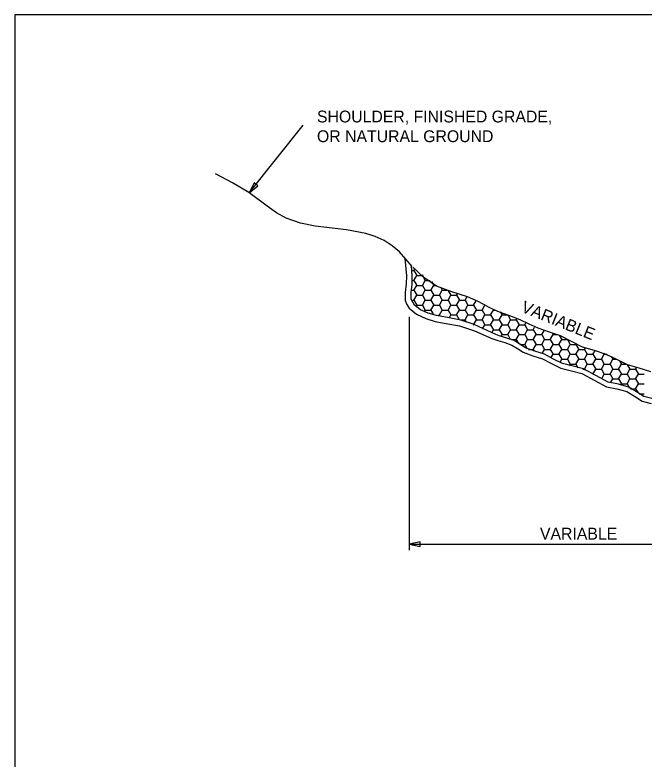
# Model space of a CAD drawing. Extents: x -439.1 to -407.9, y -458.1 to -436.2.
# Drawn here: x -439.11 to -431.12, y -447.12 to -437.68 of the extents above; entities that cross this region are included whole.
import ezdxf

# ---------------------------------------------------------------- set-up
doc = ezdxf.new("R2010")
doc.units = 0
doc.layers.add('Default', color=7, linetype='Continuous')
doc.layers.add('Draft_Named_Boundary', color=7, linetype='Continuous')

msp = doc.modelspace()

# ---------------------------------------------------------------- linework, layer by layer
at = {"layer": 'Default'}
for p, q in [((-436.134, -439.9358), (-435.4505, -439.0757)), ((-434.0746, -440.8615), (-434.1582, -440.7665)), ((-434.0677, -440.9224), (-434.0429, -440.9224)), ((-434.0429, -440.9224), (-434.0261, -440.8933)), ((-434.0429, -440.9224), (-434.0068, -440.9849)), ((-434.0429, -441.0474), (-434.0068, -440.9849)), ((-434.0068, -440.9849), (-433.9346, -440.9849)), ((-433.9346, -440.9849), (-433.9277, -440.9728)), ((-433.9346, -440.9849), (-433.8986, -441.0474)), ((-434.0672, -441.0474), (-434.0429, -441.0474)), ((-434.0429, -441.0474), (-434.0068, -441.1099)), ((-434.0429, -441.1724), (-434.0068, -441.1099)), ((-434.0068, -441.1099), (-433.9346, -441.1099)), ((-433.9346, -441.1099), (-433.8986, -441.0474)), ((-433.9346, -441.1099), (-433.8986, -441.1724)), ((-433.8986, -441.0474), (-433.8353, -441.0474)), ((-433.8264, -441.1724), (-433.7903, -441.1099)), ((-433.8186, -441.0608), (-433.7903, -441.1099)), ((-433.7903, -441.1099), (-433.7578, -441.1099)), ((-434.0666, -441.1724), (-434.0429, -441.1724)), ((-434.0429, -441.1724), (-434.0068, -441.2349)), ((-433.9346, -441.2349), (-433.8986, -441.1724)), ((-433.8986, -441.1724), (-433.8264, -441.1724)), ((-433.8264, -441.1724), (-433.7903, -441.2349)), ((-433.7181, -441.2349), (-433.682, -441.1724)), ((-433.7024, -441.137), (-433.682, -441.1724)), ((-433.682, -441.1724), (-433.6215, -441.1724)), ((-433.606, -441.1791), (-433.5738, -441.2349)), ((-433.5016, -441.2349), (-433.4904, -441.2155)), ((-434.0585, -441.2974), (-434.0429, -441.2974)), ((-434.0429, -441.2974), (-434.0068, -441.2349)), ((-434.0429, -441.2974), (-434.0068, -441.3599)), ((-434.0068, -441.2349), (-433.9346, -441.2349)), ((-433.9346, -441.2349), (-433.8986, -441.2974)), ((-433.9346, -441.3599), (-433.8986, -441.2974)), ((-433.8986, -441.2974), (-433.8264, -441.2974)), ((-433.8264, -441.2974), (-433.7903, -441.2349)), ((-433.8264, -441.2974), (-433.7903, -441.3599)), ((-433.7903, -441.2349), (-433.7181, -441.2349)), ((-433.7181, -441.2349), (-433.682, -441.2974)), ((-433.7181, -441.3599), (-433.682, -441.2974)), ((-433.682, -441.2974), (-433.6099, -441.2974)), ((-433.6099, -441.2974), (-433.5738, -441.2349)), ((-433.6099, -441.2974), (-433.5738, -441.3599)), ((-433.5738, -441.2349), (-433.5016, -441.2349)), ((-433.5016, -441.2349), (-433.4655, -441.2974)), ((-433.5016, -441.3599), (-433.4655, -441.2974)), ((-433.4655, -441.2974), (-433.3934, -441.2974)), ((-433.3934, -441.2974), (-433.3673, -441.2522)), ((-433.3934, -441.2974), (-433.3573, -441.3599)), ((-433.2851, -441.3599), (-433.2541, -441.3061)), ((-434.0125, -441.3697), (-434.0068, -441.3599)), ((-434.0068, -441.3599), (-433.9346, -441.3599)), ((-433.9346, -441.3599), (-433.8986, -441.4224)), ((-433.8264, -441.4224), (-433.7903, -441.3599)), ((-433.7903, -441.3599), (-433.7181, -441.3599)), ((-433.7181, -441.3599), (-433.682, -441.4224)), ((-433.6099, -441.4224), (-433.5738, -441.3599)), ((-433.5738, -441.3599), (-433.5016, -441.3599)), ((-433.5016, -441.3599), (-433.4655, -441.4224)), ((-433.3934, -441.4224), (-433.3573, -441.3599)), ((-433.3573, -441.3599), (-433.2851, -441.3599)), ((-433.2851, -441.3599), (-433.249, -441.4224)), ((-433.1769, -441.4224), (-433.1416, -441.3613)), ((-433.0421, -441.4058), (-433.0325, -441.4224)), ((-434.1025, -441.5089), (-434.1025, -444.4731)), ((-433.9114, -441.4446), (-433.8986, -441.4224)), ((-433.8986, -441.4224), (-433.8264, -441.4224)), ((-433.8264, -441.4224), (-433.799, -441.4697)), ((-433.7316, -441.4849), (-433.7181, -441.4849)), ((-433.7181, -441.4849), (-433.682, -441.4224)), ((-433.7181, -441.4849), (-433.7161, -441.4884)), ((-433.682, -441.4224), (-433.6099, -441.4224)), ((-433.6099, -441.4224), (-433.5738, -441.4849)), ((-433.5919, -441.5162), (-433.5738, -441.4849)), ((-433.5738, -441.4849), (-433.5016, -441.4849)), ((-433.5016, -441.4849), (-433.4655, -441.4224)), ((-433.5016, -441.4849), (-433.4674, -441.5442)), ((-433.4655, -441.4224), (-433.3934, -441.4224)), ((-433.3934, -441.4224), (-433.3573, -441.4849)), ((-433.3934, -441.5474), (-433.3573, -441.4849)), ((-433.3573, -441.4849), (-433.2851, -441.4849)), ((-433.2851, -441.4849), (-433.249, -441.4224)), ((-433.2851, -441.4849), (-433.249, -441.5474)), ((-433.249, -441.4224), (-433.1769, -441.4224)), ((-433.1769, -441.4224), (-433.1408, -441.4849)), ((-433.1769, -441.5474), (-433.1408, -441.4849)), ((-433.1408, -441.4849), (-433.0686, -441.4849)), ((-433.0686, -441.4849), (-433.0325, -441.4224)), ((-433.0686, -441.4849), (-433.0325, -441.5474)), ((-433.0325, -441.4224), (-433.0022, -441.4224)), ((-432.9604, -441.5474), (-432.9243, -441.4849)), ((-432.9471, -441.4453), (-432.9243, -441.4849)), ((-432.9243, -441.4849), (-432.8521, -441.4849)), ((-432.8521, -441.4849), (-432.8521, -441.4848)), ((-432.8521, -441.4849), (-432.816, -441.5474)), ((-433.4531, -441.5474), (-433.3934, -441.5474)), ((-433.3934, -441.5474), (-433.3774, -441.575)), ((-433.2851, -441.6099), (-433.249, -441.5474)), ((-433.249, -441.5474), (-433.1769, -441.5474)), ((-433.1769, -441.5474), (-433.1408, -441.6099)), ((-433.0686, -441.6099), (-433.0325, -441.5474)), ((-433.0325, -441.5474), (-432.9604, -441.5474)), ((-432.9604, -441.5474), (-432.9243, -441.6099)), ((-432.8521, -441.6099), (-432.816, -441.5474)), ((-432.816, -441.5474), (-432.7439, -441.5474)), ((-432.7439, -441.5474), (-432.7356, -441.5332)), ((-432.7439, -441.5474), (-432.7078, -441.6099)), ((-432.6356, -441.6099), (-432.6221, -441.5865)), ((-433.2925, -441.6099), (-433.2851, -441.6099)), ((-433.2851, -441.6099), (-433.2828, -441.6138)), ((-433.1699, -441.6602), (-433.1408, -441.6099)), ((-433.1408, -441.6099), (-433.0686, -441.6099)), ((-433.0686, -441.6099), (-433.0325, -441.6724)), ((-433.0509, -441.7041), (-433.0325, -441.6724)), ((-433.0325, -441.6724), (-432.9604, -441.6724)), ((-432.9604, -441.6724), (-432.9243, -441.6099)), ((-432.9604, -441.6724), (-432.9243, -441.7349)), ((-432.9243, -441.6099), (-432.8521, -441.6099)), ((-432.8521, -441.6099), (-432.816, -441.6724)), ((-432.8521, -441.7349), (-432.816, -441.6724)), ((-432.816, -441.6724), (-432.7439, -441.6724)), ((-432.7439, -441.6724), (-432.7078, -441.6099)), ((-432.7439, -441.6724), (-432.7078, -441.7349)), ((-432.7078, -441.6099), (-432.6356, -441.6099)), ((-432.6356, -441.6099), (-432.5995, -441.6724)), ((-432.6356, -441.7349), (-432.5995, -441.6724)), ((-432.5995, -441.6724), (-432.5273, -441.6724)), ((-432.5273, -441.6724), (-432.51, -441.6422)), ((-432.5273, -441.6724), (-432.4913, -441.7349)), ((-432.4191, -441.7349), (-432.391, -441.6862)), ((-432.9298, -441.7445), (-432.9243, -441.7349)), ((-432.9243, -441.7349), (-432.8521, -441.7349)), ((-432.8521, -441.7349), (-432.8235, -441.7845)), ((-432.8017, -441.7974), (-432.7439, -441.7974)), ((-432.7439, -441.7974), (-432.7078, -441.7349)), ((-432.7439, -441.7974), (-432.7137, -441.8496)), ((-432.7078, -441.7349), (-432.6356, -441.7349)), ((-432.6356, -441.7349), (-432.5995, -441.7974)), ((-432.6356, -441.8599), (-432.5995, -441.7974)), ((-432.5995, -441.7974), (-432.5273, -441.7974)), ((-432.5273, -441.7974), (-432.4913, -441.7349)), ((-432.5273, -441.7974), (-432.4913, -441.8599)), ((-432.4913, -441.7349), (-432.4191, -441.7349)), ((-432.4191, -441.7349), (-432.383, -441.7974)), ((-432.4191, -441.8599), (-432.383, -441.7974)), ((-432.383, -441.7974), (-432.3108, -441.7974)), ((-432.3108, -441.7974), (-432.2748, -441.7349)), ((-432.3108, -441.7974), (-432.2748, -441.8599)), ((-432.2843, -441.7183), (-432.2748, -441.7349)), ((-432.2748, -441.7349), (-432.2293, -441.7349)), ((-432.2026, -441.8599), (-432.1665, -441.7974)), ((-432.194, -441.7497), (-432.1665, -441.7974)), ((-432.1665, -441.7974), (-432.0948, -441.7974)), ((-432.6963, -441.8599), (-432.6356, -441.8599)), ((-432.6356, -441.8599), (-432.604, -441.9146)), ((-432.5273, -441.9224), (-432.4913, -441.8599)), ((-432.4913, -441.8599), (-432.4191, -441.8599)), ((-432.4191, -441.8599), (-432.383, -441.9224)), ((-432.3108, -441.9224), (-432.2748, -441.8599)), ((-432.2748, -441.8599), (-432.2026, -441.8599)), ((-432.2026, -441.8599), (-432.1665, -441.9224)), ((-432.0943, -441.9224), (-432.0583, -441.8599)), ((-432.0942, -441.7977), (-432.0583, -441.8599)), ((-432.0583, -441.8599), (-431.9861, -441.8599)), ((-431.9861, -441.8599), (-431.9814, -441.8518)), ((-431.9861, -441.8599), (-431.95, -441.9224)), ((-432.5867, -441.9224), (-432.5273, -441.9224)), ((-432.5273, -441.9224), (-432.5146, -441.9444)), ((-432.4136, -441.9753), (-432.383, -441.9224)), ((-432.383, -441.9224), (-432.3108, -441.9224)), ((-432.3108, -441.9224), (-432.2748, -441.9849)), ((-432.2987, -442.0264), (-432.2748, -441.9849)), ((-432.2748, -441.9849), (-432.2026, -441.9849)), ((-432.2026, -441.9849), (-432.1665, -441.9224)), ((-432.2026, -441.9849), (-432.1665, -442.0474)), ((-432.1665, -441.9224), (-432.0943, -441.9224)), ((-432.0943, -441.9224), (-432.0583, -441.9849)), ((-432.0943, -442.0474), (-432.0583, -441.9849)), ((-432.0583, -441.9849), (-431.9861, -441.9849)), ((-431.9861, -441.9849), (-431.95, -441.9224)), ((-431.9861, -441.9849), (-431.95, -442.0474)), ((-431.95, -441.9224), (-431.8778, -441.9224)), ((-431.8778, -441.9224), (-431.8666, -441.903)), ((-431.8778, -441.9224), (-431.8417, -441.9849)), ((-431.8778, -442.0474), (-431.8417, -441.9849)), ((-431.8417, -441.9849), (-431.7696, -441.9849)), ((-431.7696, -441.9849), (-431.7429, -441.9387)), ((-431.7696, -441.9849), (-431.7335, -442.0474)), ((-431.6613, -442.0474), (-431.6252, -441.9849)), ((-431.6337, -441.9702), (-431.6252, -441.9849)), ((-431.6252, -441.9849), (-431.5909, -441.9849)), ((-432.1879, -442.0845), (-432.1665, -442.0474)), ((-432.1665, -442.0474), (-432.0943, -442.0474)), ((-432.0943, -442.0474), (-432.0583, -442.1099)), ((-431.9861, -442.1099), (-431.95, -442.0474)), ((-431.95, -442.0474), (-431.8778, -442.0474)), ((-431.8778, -442.0474), (-431.8417, -442.1099)), ((-431.7696, -442.1099), (-431.7335, -442.0474)), ((-431.7335, -442.0474), (-431.6613, -442.0474)), ((-431.6613, -442.0474), (-431.6252, -442.1099)), ((-431.5531, -442.1099), (-431.517, -442.0474)), ((-431.5367, -442.0132), (-431.517, -442.0474)), ((-431.517, -442.0474), (-431.4714, -442.0474)), ((-431.4333, -442.0673), (-431.4087, -442.1099)), ((-432.0684, -442.1274), (-432.0583, -442.1099)), ((-432.0583, -442.1099), (-431.9861, -442.1099)), ((-431.9861, -442.1099), (-431.9597, -442.1555)), ((-431.8975, -442.1724), (-431.8778, -442.1724)), ((-431.8778, -442.1724), (-431.8417, -442.1099)), ((-431.8778, -442.1724), (-431.8699, -442.1862)), ((-431.8417, -442.1099), (-431.7696, -442.1099)), ((-431.7696, -442.1099), (-431.7335, -442.1724)), ((-431.7696, -442.2349), (-431.7335, -442.1724)), ((-431.7335, -442.1724), (-431.6613, -442.1724)), ((-431.6613, -442.1724), (-431.6252, -442.1099)), ((-431.6613, -442.1724), (-431.6252, -442.2349)), ((-431.6252, -442.1099), (-431.5531, -442.1099)), ((-431.5531, -442.1099), (-431.517, -442.1724)), ((-431.5531, -442.2349), (-431.517, -442.1724)), ((-431.517, -442.1724), (-431.4448, -442.1724)), ((-431.4448, -442.1724), (-431.4087, -442.1099)), ((-431.4448, -442.1724), (-431.4087, -442.2349)), ((-431.4087, -442.1099), (-431.3519, -442.1099)), ((-431.3366, -442.2349), (-431.3005, -442.1724)), ((-431.3299, -442.1214), (-431.3005, -442.1724)), ((-431.3005, -442.1724), (-431.2283, -442.1724)), ((-431.2283, -442.1724), (-431.2187, -442.1557)), ((-431.2283, -442.1724), (-431.1922, -442.2349)), ((-431.7725, -442.2349), (-431.7696, -442.2349)), ((-431.7696, -442.2349), (-431.7684, -442.2369)), ((-431.6582, -442.292), (-431.6252, -442.2349)), ((-431.6252, -442.2349), (-431.5531, -442.2349)), ((-431.5531, -442.2349), (-431.517, -442.2974)), ((-431.4448, -442.2974), (-431.4087, -442.2349)), ((-431.4087, -442.2349), (-431.3366, -442.2349)), ((-431.3366, -442.2349), (-431.3005, -442.2974)), ((-431.2283, -442.2974), (-431.1922, -442.2349)), ((-431.1922, -442.2349), (-431.1201, -442.2349)), ((-431.5417, -442.3402), (-431.517, -442.2974)), ((-431.517, -442.2974), (-431.4448, -442.2974)), ((-431.4448, -442.2974), (-431.4087, -442.3599)), ((-431.418, -442.376), (-431.4087, -442.3599)), ((-431.4087, -442.3599), (-431.3366, -442.3599)), ((-431.3366, -442.3599), (-431.3005, -442.2974)), ((-431.3366, -442.3599), (-431.3044, -442.4155)), ((-431.3005, -442.2974), (-431.2283, -442.2974)), ((-431.2283, -442.2974), (-431.1922, -442.3599)), ((-431.2283, -442.4224), (-431.1922, -442.3599)), ((-431.1922, -442.3599), (-431.1201, -442.3599)), ((-431.2923, -442.4224), (-431.2283, -442.4224)), ((-431.2283, -442.4224), (-431.1974, -442.476)), ((-431.1816, -442.4849), (-431.1201, -442.4849)), ((-434.1025, -444.395), (-429.662, -444.395))]:
    msp.add_line(p, q, dxfattribs=at)
for points in [[(-434.0656, -440.872), (-434.2253, -440.685), (-434.3194, -440.6057), (-434.4218, -440.5399), (-434.534, -440.4889), (-434.6523, -440.4518), (-434.9006, -440.4064), (-435.2951, -440.3589), (-435.4848, -440.3204), (-435.6634, -440.256), (-435.7867, -440.1869), (-435.9047, -440.1049), (-436.1387, -439.9323), (-436.3476, -439.806), (-436.5634, -439.6929)], [(-434.1582, -440.7665), (-434.1389, -440.9889), (-434.1402, -441.0904), (-434.1544, -441.1985), (-434.152, -441.3013), (-434.1332, -441.3519), (-434.1018, -441.3983), (-434.0091, -441.4757), (-433.8929, -441.5312), (-433.7725, -441.5671), (-433.6142, -441.5964), (-433.4659, -441.6235), (-433.2755, -441.6862)], [(-433.0039, -441.7344), (-433.2774, -441.6067), (-433.4484, -441.5506), (-433.5968, -441.5234), (-433.7552, -441.4941), (-433.8603, -441.4636), (-433.959, -441.4198), (-434.0368, -441.3608), (-434.0789, -441.2847), (-434.0795, -441.1948), (-434.0656, -441.0982), (-434.0639, -440.9897), (-434.0746, -440.8615)], [(-433.0995, -441.382), (-433.2287, -441.3154), (-433.3618, -441.257), (-433.561, -441.1928), (-433.7552, -441.1187), (-433.917, -441.0117), (-434.0584, -440.8768)], [(-433.0995, -441.382), (-433.0299, -441.4145), (-432.9594, -441.4448), (-432.8283, -441.4918), (-432.6983, -441.5409), (-432.5842, -441.5964), (-432.4696, -441.6502), (-432.3276, -441.6976), (-432.1862, -441.7463), (-432.0458, -441.818), (-431.9049, -441.888), (-431.7556, -441.9344), (-431.6063, -441.9811), (-431.4705, -442.0486), (-431.3341, -442.1147), (-431.1864, -442.1576), (-431.0406, -442.2047)], [(-433.2755, -441.6862), (-433.0518, -441.7833), (-432.9773, -441.8109), (-432.8865, -441.8358), (-432.7989, -441.8671), (-432.7271, -441.9113), (-432.6556, -441.9564), (-432.5346, -442.0022), (-432.4106, -442.0428), (-432.2943, -442.1034), (-432.1774, -442.1612), (-432.044, -442.1941), (-431.9109, -442.2277), (-431.7545, -442.3146), (-431.5966, -442.3977), (-431.4672, -442.4241), (-431.3408, -442.4569), (-431.2439, -442.5179), (-431.1465, -442.5778), (-431.0289, -442.6086)], [(-431.0062, -442.5503), (-431.1216, -442.5205), (-431.2185, -442.4608), (-431.3149, -442.4001), (-431.4444, -442.3659), (-431.577, -442.3383), (-431.7336, -442.2557), (-431.8887, -442.1693), (-432.0221, -442.1356), (-432.1558, -442.1025), (-432.2714, -442.0452), (-432.3866, -441.9852), (-432.5079, -441.9457), (-432.6264, -441.9012), (-432.6986, -441.8556), (-432.7711, -441.8111), (-432.8631, -441.7779), (-432.9583, -441.7514), (-433.0039, -441.7344)]]:
    msp.add_lwpolyline(points, dxfattribs=at)
for points in [[(-436.0704, -439.8097), (-436.134, -439.9358), (-436.0254, -439.8454)], [(-436.0704, -439.8097), (-436.134, -439.9358), (-436.0254, -439.8454)], [(-433.9643, -444.3663), (-434.1025, -444.395), (-433.9643, -444.4237)]]:
    msp.add_lwpolyline(points, close=True, dxfattribs=at)
at = {"layer": 'Draft_Named_Boundary'}
msp.add_lwpolyline([(-439.109, -458.0508), (-407.859, -458.0508), (-407.859, -437.6758), (-439.109, -437.6758)], close=True, dxfattribs=at)

# ---------------------------------------------------------------- texts
at = {"layer": 'Default'}
for s, p in [('SHOULDER, FINISHED GRADE,', (-435.2734, -439.0412)), ('OR NATURAL GROUND', (-435.2734, -439.2912)), ('VARIABLE', (-432.4425, -444.3366))]:
    msp.add_text(s, height=0.15, dxfattribs=at).set_placement(p)
msp.add_text('VARIABLE', height=0.15, rotation=338, dxfattribs=at).set_placement((-432.6919, -441.4406))

doc.saveas('drawing.dxf')
